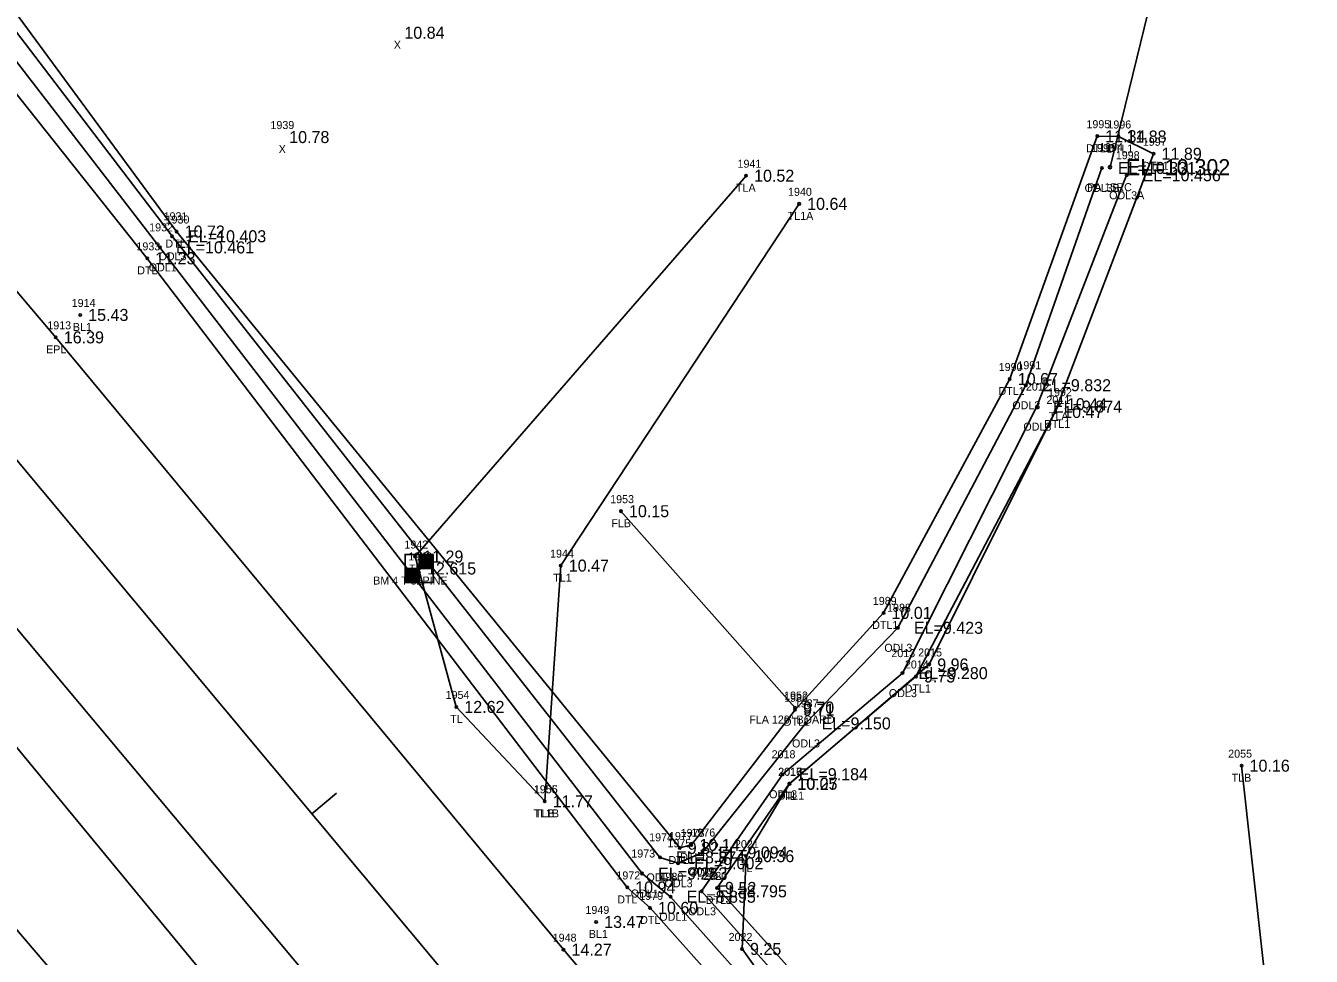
# Model space of a CAD drawing. Extents: x 2042117 to 2045853, y 303080 to 309569.
# Drawn here: x 2044074.2 to 2044234.8, y 305116.8 to 305233.1 of the extents above; entities that cross this region are included whole.
import ezdxf

# ---------------------------------------------------------------- set-up
doc = ezdxf.new("R2010")
doc.units = 0
for name, color, linetype in [('RD_DTM_BkLn_txCode', 7, 'Continuous'), ('RD_EX_DR_Pipe', 7, 'Continuous'), ('RD_EX_DR_Pipe_txCode', 7, 'Continuous'), ('RD_EX_Fence_Other', 7, 'Continuous'), ('RD_EX_Fence_Other_txCode', 7, 'Continuous'), ('RD_EX_H2O', 7, 'Continuous'), ('RD_EX_H2O_txCode', 7, 'Continuous'), ('RD_EX_Misc_txCode', 7, 'Continuous'), ('RD_EX_Road', 7, 'Continuous'), ('RD_EX_Road_txCode', 7, 'Continuous'), ('RD_EX_TX_Fence_Other_ELEV', 7, 'Continuous'), ('RD_EX_TX_H2O_ELEV', 7, 'Continuous'), ('RD_EX_TX_Misc_ELEV', 7, 'Continuous'), ('RD_EX_TX_Road_ELEV', 7, 'Continuous'), ('RD_EX_TX_VEG_ELEV', 7, 'Continuous'), ('RD_EX_VEG', 7, 'Continuous'), ('RD_EX_VEG_txCode', 7, 'Continuous'), ('RD_HC_Cl', 7, 'Continuous'), ('RD_HC_Data_Tic', 7, 'Continuous'), ('RD_HC_Survey', 7, 'Continuous'), ('RD_HC_Survey_ELEV', 7, 'Continuous'), ('RD_HC_Survey_txCode', 7, 'Continuous'), ('RD_SMD_Locator', 7, 'Continuous'), ('RD_TX_Pipe_ElevEX', 7, 'Continuous')]:
    doc.layers.add(name, color=color, linetype=linetype)

msp = doc.modelspace()

# ---------------------------------------------------------------- linework, layer by layer
at = {"layer": 'RD_EX_DR_Pipe'}
msp.add_line((2044209.68, 305215.41), (2044215.36, 305238.61), dxfattribs=at)
at = {"layer": 'RD_EX_Fence_Other'}
msp.add_line((2044170.31, 305147.91), (2044148.58, 305172.44), dxfattribs=at)
at = {"layer": 'RD_EX_H2O'}
for points in [[(2043695.41, 305785.95), (2043753.23, 305702.74), (2043816.84, 305621.67), (2043878.98, 305542.47), (2043936.42, 305466.41), (2044001.08, 305383.06), (2044036.64, 305336.24), (2044042.32, 305312.25), (2044044.08, 305296.68), (2044037.04, 305284.58), (2044037.23, 305281.89), (2044040.11, 305279.62), (2044044.74, 305276.06), (2044050.89, 305261.28), (2044092.5, 305206.78), (2044153.45, 305129.2), (2044155.72, 305128.46), (2044158.75, 305129.8), (2044171.64, 305145.93), (2044183.17, 305157.87), (2044199.16, 305188.17), (2044208.66, 305215.31)], [(2044033.22, 305275.98), (2044035.9, 305278.5), (2044040.04, 305277.28), (2044042.29, 305273.95), (2044048.6, 305260.29), (2044090.99, 305205.39), (2044151.22, 305127.18), (2044154.78, 305124.28), (2044202.92, 305070.22), (2044216.63, 305053.71), (2044279.58, 304974.12), (2044337.99, 304907.57), (2044344.68, 304901.99)], [(2044036.31, 305275.77), (2044038.93, 305275.76), (2044040.37, 305274.17), (2044045.78, 305258.87), (2044089.4, 305204.02), (2044149.36, 305125.44), (2044152.21, 305122.89), (2044203.11, 305065.8), (2044214.18, 305051.6), (2044278.81, 304973.18), (2044336.46, 304906.31), (2044343.82, 304899.94), (2044347.6, 304901.86)], [(2044052.64, 305262.28), (2044093.07, 305207.37), (2044155.92, 305130.37), (2044157.38, 305130.75), (2044170.33, 305147.63), (2044181.38, 305159.73), (2044197.15, 305188.95), (2044208.08, 305219.28), (2044210.72, 305219.24), (2044215.12, 305217.08), (2044202.83, 305184.83), (2044185.43, 305151.79), (2044169.6, 305138.4), (2044160.58, 305125.38), (2044211.54, 305068.64), (2044219.9, 305056.44), (2044285.19, 304978.84), (2044339.94, 304911.4), (2044347.53, 304904.82), (2044347.6, 304901.86)], [(2044211.75, 305214.4), (2044200.54, 305185.5), (2044183.75, 305152.21), (2044168.79, 305139.58), (2044158.66, 305124.96), (2044210.53, 305066.67), (2044218.51, 305055.53), (2044282.21, 304976.06), (2044339.42, 304909.19), (2044345.98, 304903.69)]]:
    msp.add_lwpolyline(points, dxfattribs=at)
at = {"layer": 'RD_EX_Road'}
for points in [[(2043522.11, 305820), (2043547.67, 305789.85), (2043610.72, 305713.32), (2043674.95, 305636.32), (2043738.18, 305559.62), (2043802.42, 305482.71), (2043865.72, 305405.84), (2043929.53, 305328.85), (2043994.13, 305253.28), (2044057.4, 305176.5), (2044121.27, 305100.2), (2044185.29, 305023.54), (2044249.56, 304947.28), (2044313.31, 304870.31), (2044377.09, 304793.29), (2044442, 304716.26), (2044505.92, 304639.55), (2044570.44, 304562.35), (2044634.61, 304485.93), (2044698.46, 304409.27), (2044762.46, 304332.37)], [(2043821.87, 305499.1), (2043885.81, 305423.07), (2043949.56, 305345.93), (2044013.41, 305270.34), (2044077.97, 305194.15), (2044141.4, 305117.67), (2044205.92, 305040.83), (2044269.54, 304964.65), (2044331.73, 304891.04), (2044335.22, 304889.2), (2044346.01, 304875.31), (2044356.18, 304867.61), (2044370.01, 304868.14), (2044386.83, 304866.36), (2044389.44, 304849.53), (2044390.71, 304830.73), (2044393.77, 304818.44), (2044395.5, 304814.18), (2044398.16, 304811.09)]]:
    msp.add_lwpolyline(points, dxfattribs=at)
at = {"layer": 'RD_EX_VEG'}
for points in [[(2043981.22, 305231.74), (2043985.09, 305231.71), (2043988, 305235.21), (2044050.29, 305170.52), (2044112.48, 305095.16), (2044104.33, 305083.55)], [(2043981.22, 305231.74), (2044037.19, 305162.16), (2044104.33, 305083.55)], [(2044164.21, 305214.34), (2044122.87, 305166.77), (2044128.01, 305147.99), (2044139.06, 305136.2)], [(2044170.84, 305210.83), (2044141.06, 305165.64), (2044139.06, 305136.2)], [(2044203.29, 305185.8), (2044187.09, 305153.29), (2044169.64, 305138.38), (2044164.21, 305129.35), (2044163.7, 305117.76), (2044206.63, 305057.39), (2044230.52, 305052.69), (2044229.62, 305068.74), (2044231.4, 305092.87), (2044226.11, 305140.65)]]:
    msp.add_lwpolyline(points, dxfattribs=at)
at = {"layer": 'RD_HC_Cl'}
msp.add_line((2043284.3, 306123.24), (2045221.31, 303804), dxfattribs=at)
at = {"layer": 'RD_HC_Data_Tic'}
msp.add_line((2044109.97, 305134.64), (2044113.04, 305137.2), dxfattribs=at)
at = {"layer": 'RD_HC_Survey'}
for p, q in [((2044123.35, 305167.03), (2044123.35, 305163.53)), ((2044123.37, 305167.03), (2044123.37, 305165.28)), ((2044123.39, 305167.03), (2044123.39, 305165.28)), ((2044123.42, 305167.03), (2044123.42, 305165.28)), ((2044123.44, 305167.03), (2044123.44, 305165.28)), ((2044123.47, 305167.03), (2044123.47, 305165.28)), ((2044123.49, 305167.03), (2044123.49, 305165.28)), ((2044123.52, 305167.03), (2044123.52, 305165.28)), ((2044123.54, 305167.03), (2044123.54, 305165.28)), ((2044123.57, 305167.03), (2044123.57, 305165.28)), ((2044123.59, 305167.03), (2044123.59, 305165.28)), ((2044123.62, 305167.03), (2044123.62, 305165.28)), ((2044123.64, 305167.03), (2044123.64, 305165.28)), ((2044123.67, 305167.03), (2044123.67, 305165.28)), ((2044123.69, 305167.03), (2044123.69, 305165.28)), ((2044123.72, 305167.03), (2044123.72, 305165.28)), ((2044123.74, 305167.03), (2044123.74, 305165.28)), ((2044123.77, 305167.03), (2044123.77, 305165.28)), ((2044123.79, 305167.03), (2044123.79, 305165.28)), ((2044123.82, 305167.03), (2044123.82, 305165.28)), ((2044123.84, 305167.03), (2044123.84, 305165.28)), ((2044123.87, 305167.03), (2044123.87, 305165.28)), ((2044123.89, 305167.03), (2044123.89, 305165.28)), ((2044123.91, 305167.03), (2044123.91, 305165.28)), ((2044123.94, 305167.03), (2044123.94, 305165.28)), ((2044123.96, 305167.03), (2044123.96, 305165.28)), ((2044123.99, 305167.03), (2044123.99, 305165.28)), ((2044124.01, 305167.03), (2044124.01, 305165.28)), ((2044124.04, 305167.03), (2044124.04, 305165.28)), ((2044124.06, 305167.03), (2044124.06, 305165.28)), ((2044124.09, 305167.03), (2044124.09, 305165.28)), ((2044124.11, 305167.03), (2044124.11, 305165.28)), ((2044124.14, 305167.03), (2044124.14, 305165.28)), ((2044124.16, 305167.03), (2044124.16, 305165.28)), ((2044124.19, 305167.03), (2044124.19, 305165.28)), ((2044124.21, 305167.03), (2044124.21, 305165.28)), ((2044124.24, 305167.03), (2044124.24, 305165.28)), ((2044124.26, 305167.03), (2044124.26, 305165.28)), ((2044124.29, 305167.03), (2044124.29, 305165.28)), ((2044124.31, 305167.03), (2044124.31, 305165.28)), ((2044124.34, 305167.03), (2044124.34, 305165.28)), ((2044124.36, 305167.03), (2044124.36, 305165.28)), ((2044124.38, 305167.03), (2044124.38, 305165.28)), ((2044124.41, 305167.03), (2044124.41, 305165.28)), ((2044124.43, 305167.03), (2044124.43, 305165.28)), ((2044124.46, 305167.03), (2044124.46, 305165.28)), ((2044124.48, 305167.03), (2044124.48, 305165.28)), ((2044124.51, 305167.03), (2044124.51, 305165.28)), ((2044124.53, 305167.03), (2044124.53, 305165.28)), ((2044124.56, 305167.03), (2044124.56, 305165.28)), ((2044124.58, 305167.03), (2044124.58, 305165.28)), ((2044124.61, 305167.03), (2044124.61, 305165.28)), ((2044124.63, 305167.03), (2044124.63, 305165.28)), ((2044124.66, 305167.03), (2044124.66, 305165.28)), ((2044124.68, 305167.03), (2044124.68, 305165.28)), ((2044124.71, 305167.03), (2044124.71, 305165.28)), ((2044124.73, 305167.03), (2044124.73, 305165.28)), ((2044124.76, 305167.03), (2044124.76, 305165.28)), ((2044124.78, 305167.03), (2044124.78, 305165.28)), ((2044124.81, 305167.03), (2044124.81, 305165.28)), ((2044124.83, 305167.03), (2044124.83, 305165.28)), ((2044124.86, 305167.03), (2044124.86, 305165.28)), ((2044124.88, 305167.03), (2044124.88, 305165.28)), ((2044124.9, 305167.03), (2044124.9, 305165.28)), ((2044124.93, 305167.03), (2044124.93, 305165.28)), ((2044124.95, 305167.03), (2044124.95, 305165.28)), ((2044124.98, 305167.03), (2044124.98, 305165.28)), ((2044125, 305167.03), (2044125, 305165.28)), ((2044125.03, 305167.03), (2044125.03, 305165.28)), ((2044125.05, 305167.03), (2044125.05, 305165.28)), ((2044125.08, 305167.03), (2044125.08, 305165.28)), ((2044125.1, 305165.28), (2044121.6, 305165.28)), ((2044121.6, 305165.28), (2044121.6, 305163.53)), ((2044121.63, 305165.28), (2044121.63, 305163.53)), ((2044121.65, 305165.28), (2044121.65, 305163.53)), ((2044121.68, 305165.28), (2044121.68, 305163.53)), ((2044121.7, 305165.28), (2044121.7, 305163.53)), ((2044121.73, 305165.28), (2044121.73, 305163.53)), ((2044121.75, 305165.28), (2044121.75, 305163.53)), ((2044121.78, 305165.28), (2044121.78, 305163.53)), ((2044121.8, 305165.28), (2044121.8, 305163.53)), ((2044121.83, 305165.28), (2044121.83, 305163.53)), ((2044121.85, 305165.28), (2044121.85, 305163.53)), ((2044121.87, 305165.28), (2044121.87, 305163.53)), ((2044121.9, 305165.28), (2044121.9, 305163.53)), ((2044121.92, 305165.28), (2044121.92, 305163.53)), ((2044121.95, 305165.28), (2044121.95, 305163.53)), ((2044121.97, 305165.28), (2044121.97, 305163.53)), ((2044122, 305165.28), (2044122, 305163.53)), ((2044122.02, 305165.28), (2044122.02, 305163.53)), ((2044122.05, 305165.28), (2044122.05, 305163.53)), ((2044122.07, 305165.28), (2044122.07, 305163.53)), ((2044122.1, 305165.28), (2044122.1, 305163.53)), ((2044122.12, 305165.28), (2044122.12, 305163.53)), ((2044122.15, 305165.28), (2044122.15, 305163.53)), ((2044122.17, 305165.28), (2044122.17, 305163.53)), ((2044122.2, 305165.28), (2044122.2, 305163.53)), ((2044122.22, 305165.28), (2044122.22, 305163.53)), ((2044122.25, 305165.28), (2044122.25, 305163.53)), ((2044122.27, 305165.28), (2044122.27, 305163.53)), ((2044122.3, 305165.28), (2044122.3, 305163.53)), ((2044122.32, 305165.28), (2044122.32, 305163.53)), ((2044122.34, 305165.28), (2044122.34, 305163.53)), ((2044122.37, 305165.28), (2044122.37, 305163.53)), ((2044122.39, 305165.28), (2044122.39, 305163.53)), ((2044122.42, 305165.28), (2044122.42, 305163.53)), ((2044122.44, 305165.28), (2044122.44, 305163.53)), ((2044122.47, 305165.28), (2044122.47, 305163.53)), ((2044122.49, 305165.28), (2044122.49, 305163.53)), ((2044122.52, 305165.28), (2044122.52, 305163.53)), ((2044122.54, 305165.28), (2044122.54, 305163.53)), ((2044122.57, 305165.28), (2044122.57, 305163.53)), ((2044122.59, 305165.28), (2044122.59, 305163.53)), ((2044122.62, 305165.28), (2044122.62, 305163.53)), ((2044122.64, 305165.28), (2044122.64, 305163.53)), ((2044122.67, 305165.28), (2044122.67, 305163.53)), ((2044122.69, 305165.28), (2044122.69, 305163.53)), ((2044122.72, 305165.28), (2044122.72, 305163.53)), ((2044122.74, 305165.28), (2044122.74, 305163.53)), ((2044122.77, 305165.28), (2044122.77, 305163.53)), ((2044122.79, 305165.28), (2044122.79, 305163.53)), ((2044122.82, 305165.28), (2044122.82, 305163.53)), ((2044122.84, 305165.28), (2044122.84, 305163.53)), ((2044122.86, 305165.28), (2044122.86, 305163.53)), ((2044122.89, 305165.28), (2044122.89, 305163.53)), ((2044122.91, 305165.28), (2044122.91, 305163.53)), ((2044122.94, 305165.28), (2044122.94, 305163.53)), ((2044122.96, 305165.28), (2044122.96, 305163.53)), ((2044122.99, 305165.28), (2044122.99, 305163.53)), ((2044123.01, 305165.28), (2044123.01, 305163.53)), ((2044123.04, 305165.28), (2044123.04, 305163.53)), ((2044123.06, 305165.28), (2044123.06, 305163.53)), ((2044123.09, 305165.28), (2044123.09, 305163.53)), ((2044123.11, 305165.28), (2044123.11, 305163.53)), ((2044123.14, 305165.28), (2044123.14, 305163.53)), ((2044123.16, 305165.28), (2044123.16, 305163.53)), ((2044123.19, 305165.28), (2044123.19, 305163.53)), ((2044123.21, 305165.28), (2044123.21, 305163.53)), ((2044123.24, 305165.28), (2044123.24, 305163.53)), ((2044123.26, 305165.28), (2044123.26, 305163.53)), ((2044123.29, 305165.28), (2044123.29, 305163.53)), ((2044123.31, 305165.28), (2044123.31, 305163.53)), ((2044123.33, 305165.28), (2044123.33, 305163.53))]:
    msp.add_line(p, q, dxfattribs=at)
msp.add_lwpolyline([(2044125.1, 305167.03), (2044121.6, 305167.03), (2044121.6, 305163.53), (2044125.1, 305163.53)], close=True, dxfattribs=at)
at = {"layer": 'RD_SMD_Locator'}
for centre, radius in [((2044208.08, 305219.28), 0.15), ((2044210.72, 305219.24), 0.15), ((2044215.12, 305217.08), 0.15), ((2044208.66, 305215.31), 0.15), ((2044209.68, 305215.41), 0.2), ((2044164.21, 305214.34), 0.15), ((2044211.75, 305214.4), 0.15), ((2044170.84, 305210.83), 0.15), ((2044092.5, 305206.78), 0.15), ((2044093.07, 305207.37), 0.15), ((2044090.99, 305205.39), 0.15), ((2044089.4, 305204.02), 0.15), ((2044081.02, 305196.95), 0.15), ((2044077.97, 305194.15), 0.15), ((2044197.15, 305188.95), 0.15), ((2044199.16, 305188.17), 0.15), ((2044203.29, 305185.8), 0.15), ((2044200.54, 305185.5), 0.15), ((2044202.83, 305184.83), 0.15), ((2044148.58, 305172.44), 0.15), ((2044122.87, 305166.77), 0.15), ((2044123.35, 305165.28), 0.15), ((2044141.06, 305165.64), 0.15), ((2044181.38, 305159.73), 0.15), ((2044183.17, 305157.87), 0.15), ((2044183.75, 305152.21), 0.15), ((2044187.09, 305153.29), 0.15), ((2044185.43, 305151.79), 0.15), ((2044128.01, 305147.99), 0.15), ((2044170.31, 305147.91), 0.15), ((2044170.33, 305147.63), 0.15), ((2044171.64, 305145.93), 0.15), ((2044226.11, 305140.65), 0.15), ((2044168.79, 305139.58), 0.15), ((2044169.6, 305138.4), 0.15), ((2044169.64, 305138.38), 0.15), ((2044139.06, 305136.2), 0.15), ((2044139.06, 305136.2), 0.15), ((2044155.92, 305130.37), 0.15), ((2044157.38, 305130.75), 0.15), ((2044158.75, 305129.8), 0.15), ((2044153.45, 305129.2), 0.15), ((2044155.72, 305128.46), 0.15), ((2044164.21, 305129.35), 0.15), ((2044151.22, 305127.18), 0.15), ((2044149.36, 305125.44), 0.15), ((2044158.66, 305124.96), 0.15), ((2044160.58, 305125.38), 0.15), ((2044154.78, 305124.28), 0.15), ((2044152.21, 305122.89), 0.15), ((2044145.48, 305121.13), 0.15), ((2044141.4, 305117.67), 0.15), ((2044163.7, 305117.76), 0.15)]:
    msp.add_circle(centre, radius, dxfattribs=at)

# ---------------------------------------------------------------- texts
at = {"layer": 'RD_DTM_BkLn_txCode'}
for s, p in [('1914', (2044079.96, 305197.95)), ('BL1', (2044080.1, 305194.95)), ('1949', (2044144.14, 305122.13)), ('BL1', (2044144.56, 305119.13))]:
    msp.add_text(s, height=1, dxfattribs=at).set_placement(p)
at = {"layer": 'RD_EX_DR_Pipe_txCode'}
for s, p in [('1994', (2044208.33, 305217.41)), ('PA 15RC', (2044206.83, 305212.41))]:
    msp.add_text(s, height=1, dxfattribs=at).set_placement(p)
at = {"layer": 'RD_EX_Fence_Other_txCode'}
for s, p in [('1953', (2044147.23, 305173.44)), ('FLB', (2044147.38, 305170.44)), ('1952', (2044168.96, 305148.91)), ('FLA 120" BOARD', (2044164.61, 305145.91))]:
    msp.add_text(s, height=1, dxfattribs=at).set_placement(p)
at = {"layer": 'RD_EX_H2O_txCode'}
for s, p in [('1995', (2044206.73, 305220.28)), ('1996', (2044209.35, 305220.24)), ('DTL1', (2044206.67, 305217.28)), ('1993', (2044207.31, 305217.31)), ('DTL1', (2044209.31, 305217.24)), ('1997', (2044213.77, 305218.08)), ('1998', (2044210.4, 305216.4)), ('DTL1', (2044213.71, 305215.08)), ('ODL3B', (2044206.5, 305212.31)), ('ODL3A', (2044209.57, 305211.4)), ('1932', (2044089.64, 305207.39)), ('1931', (2044091.44, 305208.78)), ('1930', (2044091.69, 305208.37)), ('1933', (2044088.05, 305205.02)), ('DTL1', (2044091.66, 305205.37)), ('ODL3', (2044090.81, 305203.78)), ('DTL', (2044088.15, 305202.02)), ('ODL1', (2044089.58, 305202.39)), ('1990', (2044195.77, 305189.95)), ('1991', (2044198.1, 305190.17)), ('DTL1', (2044195.74, 305186.95)), ('2012', (2044199.16, 305187.5)), ('ODL3', (2044197.47, 305185.17)), ('2011', (2044201.73, 305185.83)), ('ODL3', (2044198.85, 305182.5)), ('DTL1', (2044201.43, 305182.83)), ('1989', (2044180.04, 305160.73)), ('1988', (2044181.82, 305159.87)), ('DTL1', (2044179.97, 305157.73)), ('ODL3', (2044181.48, 305154.87)), ('2013', (2044182.36, 305154.21)), ('2014', (2044184.05, 305152.79)), ('DTL1', (2044184.02, 305149.79)), ('1986', (2044168.96, 305148.63)), ('1987', (2044170.29, 305147.93)), ('ODL3', (2044182.05, 305149.21)), ('DTL1', (2044168.92, 305145.63)), ('2018', (2044167.4, 305141.58)), ('ODL3', (2044169.95, 305142.93)), ('2017', (2044168.21, 305139.4)), ('ODL3', (2044167.09, 305136.58)), ('DTL1', (2044168.19, 305136.4)), ('1978', (2044156.04, 305131.75)), ('1976', (2044157.38, 305131.8)), ('1974', (2044152.1, 305131.2)), ('1975', (2044154.38, 305130.46)), ('1977', (2044154.57, 305131.37)), ('1973', (2044149.87, 305129.18)), ('DTL1', (2044155.97, 305128.75)), ('DTL1', (2044154.51, 305128.37)), ('2019', (2044157.27, 305126.96)), ('1972', (2044148.01, 305126.44)), ('ODL3', (2044151.76, 305126.2)), ('1980', (2044153.39, 305126.28)), ('ODL3', (2044154.03, 305125.46)), ('ODL3', (2044157.06, 305126.8)), ('2020', (2044158.87, 305126.38)), ('ODL1', (2044149.81, 305124.18)), ('1979', (2044150.87, 305123.89)), ('DTL', (2044148.12, 305123.44)), ('DTL1', (2044159.17, 305123.38)), ('DTL', (2044150.97, 305120.89)), ('ODL1', (2044153.37, 305121.28)), ('ODL3', (2044156.96, 305121.96))]:
    msp.add_text(s, height=1, dxfattribs=at).set_placement(p)
at = {"layer": 'RD_EX_Misc_txCode'}
for s, p in [('X', (2044120.2, 305230.2)), ('1939', (2044104.79, 305220.17)), ('X', (2044105.82, 305217.17))]:
    msp.add_text(s, height=1, dxfattribs=at).set_placement(p)
at = {"layer": 'RD_EX_Road_txCode'}
for s, p in [('1913', (2044076.91, 305195.15)), ('EPL', (2044076.76, 305192.15)), ('1948', (2044140.05, 305118.67))]:
    msp.add_text(s, height=1, dxfattribs=at).set_placement(p)
at = {"layer": 'RD_EX_TX_Fence_Other_ELEV'}
for s, p in [('10.15', (2044149.58, 305171.69)), ('9.70', (2044171.31, 305147.16))]:
    msp.add_text(s, height=1.5, dxfattribs=at).set_placement(p)
at = {"layer": 'RD_EX_TX_H2O_ELEV'}
for s, p in [('11.34', (2044209.08, 305218.53)), ('11.88', (2044211.72, 305218.49)), ('11.89', (2044216.12, 305216.33)), ('EL=10.331', (2044210.66, 305214.56)), ('EL=10.456', (2044213.75, 305213.65)), ('10.72', (2044094.07, 305206.62)), ('EL=10.403', (2044094.5, 305206.03)), ('EL=10.461', (2044092.99, 305204.64)), ('11.23', (2044090.4, 305203.27)), ('10.67', (2044198.15, 305188.2)), ('EL=9.832', (2044201.16, 305187.42)), ('EL=9.874', (2044202.54, 305184.75)), ('10.47', (2044203.83, 305184.08)), ('10.01', (2044182.38, 305158.98)), ('EL=9.423', (2044185.17, 305157.12)), ('EL=9.280', (2044185.75, 305151.46)), ('9.75', (2044186.43, 305151.04)), ('9.71', (2044171.33, 305146.88)), ('EL=9.150', (2044173.64, 305145.18)), ('EL=9.184', (2044170.79, 305138.83)), ('10.05', (2044170.6, 305137.65)), ('10.14', (2044158.38, 305130)), ('EL=8.874', (2044155.45, 305128.45)), ('9.82', (2044156.92, 305129.62)), ('EL=9.094', (2044160.75, 305129.05)), ('EL=9.253', (2044153.22, 305126.43)), ('EL=9.002', (2044157.72, 305127.71)), ('10.94', (2044150.36, 305124.69)), ('EL=8.895', (2044156.78, 305123.53)), ('EL=8.795', (2044160.66, 305124.21)), ('9.52', (2044161.58, 305124.63)), ('10.60', (2044153.21, 305122.14))]:
    msp.add_text(s, height=1.5, dxfattribs=at).set_placement(p)
at = {"layer": 'RD_EX_TX_Misc_ELEV'}
for s, p in [('10.84', (2044121.52, 305231.45)), ('10.78', (2044107.13, 305218.42)), ('15.43', (2044082.02, 305196.2)), ('13.47', (2044146.48, 305120.38))]:
    msp.add_text(s, height=1.5, dxfattribs=at).set_placement(p)
at = {"layer": 'RD_EX_TX_Road_ELEV'}
for s, p in [('16.39', (2044078.97, 305193.4)), ('14.27', (2044142.4, 305116.92))]:
    msp.add_text(s, height=1.5, dxfattribs=at).set_placement(p)
at = {"layer": 'RD_EX_TX_VEG_ELEV'}
for s, p in [('10.52', (2044165.21, 305213.59)), ('10.64', (2044171.84, 305210.08)), ('10.44', (2044204.29, 305185.05)), ('11.29', (2044123.87, 305166.02)), ('10.47', (2044142.06, 305164.89)), ('9.96', (2044188.09, 305152.54)), ('12.62', (2044129.01, 305147.24)), ('10.16', (2044227.11, 305139.9)), ('10.27', (2044170.64, 305137.63)), ('11.77', (2044140.06, 305135.45)), ('11.77', (2044140.06, 305135.45)), ('10.36', (2044165.21, 305128.6)), ('9.25', (2044164.7, 305117.01))]:
    msp.add_text(s, height=1.5, dxfattribs=at).set_placement(p)
at = {"layer": 'RD_EX_VEG_txCode'}
for s, p in [('1941', (2044163.14, 305215.34)), ('TLA', (2044162.95, 305212.34)), ('1940', (2044169.45, 305211.83)), ('TL1A', (2044169.41, 305208.83)), ('1992', (2044201.94, 305186.8)), ('TLA', (2044202.03, 305183.8)), ('1942', (2044121.52, 305167.77)), ('1944', (2044139.72, 305166.64)), ('TL', (2044122.1, 305164.77)), ('TL1', (2044140.12, 305163.64)), ('2015', (2044185.71, 305154.29)), ('TL', (2044186.32, 305151.29)), ('1954', (2044126.67, 305148.99)), ('TL', (2044127.24, 305145.99)), ('2055', (2044224.44, 305141.65)), ('2016', (2044168.23, 305139.38)), ('TLB', (2044224.87, 305138.65)), ('1956', (2044137.69, 305137.2)), ('1955', (2044137.71, 305137.2)), ('TL', (2044168.87, 305136.38)), ('TL1B', (2044137.65, 305134.2)), ('TLB', (2044137.81, 305134.2)), ('2021', (2044162.82, 305130.35)), ('TL', (2044163.43, 305127.35)), ('2022', (2044162.03, 305118.76))]:
    msp.add_text(s, height=1, dxfattribs=at).set_placement(p)
at = {"layer": 'RD_HC_Survey_ELEV'}
msp.add_text('12.615', height=1.5, dxfattribs=at).set_placement((2044124.35, 305164.53))
at = {"layer": 'RD_HC_Survey_txCode'}
for s, p in [('1943', (2044122.01, 305166.28)), ('BM 4 T 32PINE', (2044117.62, 305163.28))]:
    msp.add_text(s, height=1, dxfattribs=at).set_placement(p)
at = {"layer": 'RD_TX_Pipe_ElevEX'}
msp.add_text('EL=10.302', height=2, dxfattribs=at).set_placement((2044211.68, 305214.41))

doc.saveas('drawing.dxf')
